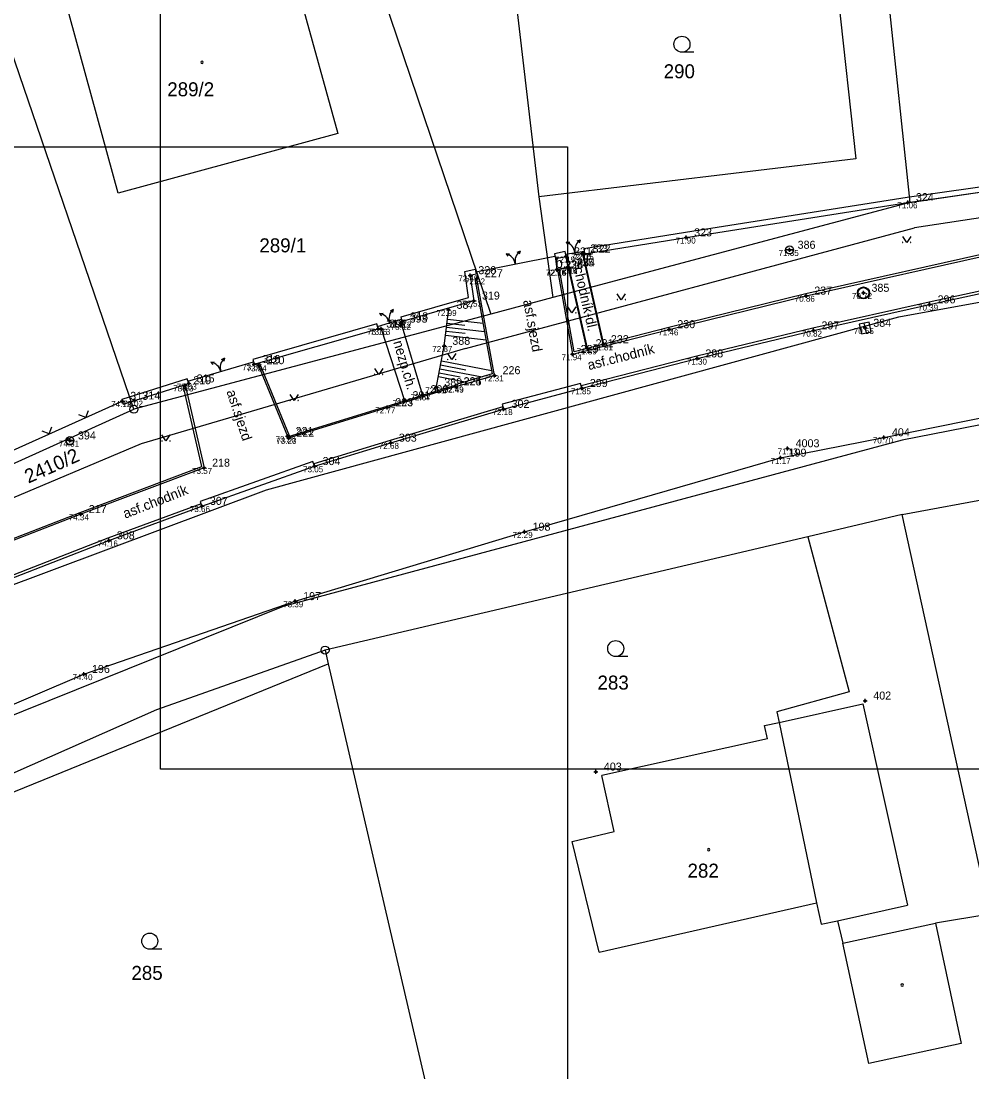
# Model space of a CAD drawing. Extents: x -454285 to -453563, y -1108687 to -1108249.
# Drawn here: x -453975.4 to -453927.9, y -1108516.1 to -1108463.6 of the extents above; entities that cross this region are included whole.
import ezdxf

# ---------------------------------------------------------------- set-up
doc = ezdxf.new("R2010")
doc.units = 0
for name, color, linetype in [('1', 7, 'Continuous'), ('14', 7, 'Continuous'), ('15', 7, 'Continuous'), ('2', 7, 'Continuous'), ('23', 7, 'Continuous'), ('25', 7, 'Continuous'), ('28', 7, 'Continuous'), ('beton', 7, 'Continuous'), ('BODY_T1_2018', 7, 'Continuous'), ('CISLA_T1_2018', 7, 'Continuous'), ('nezp.chodník', 7, 'Continuous'), ('obrubník', 7, 'Continuous'), ('okraj asf.komunikace', 7, 'Continuous'), ('oplocení', 7, 'Continuous'), ('rámy', 7, 'Continuous'), ('sloup', 7, 'Continuous'), ('svahy', 7, 'Continuous'), ('svahy-hrana', 7, 'Continuous'), ('T', 7, 'Continuous'), ('uliční vpusť', 7, 'Continuous'), ('VYSKY_T1_2018', 7, 'Continuous'), ('zeleň', 7, 'Continuous'), ('šachtice', 7, 'Continuous')]:
    doc.layers.add(name, color=color, linetype=linetype)

# ---------------------------------------------------------------- blocks, each defined once
blk = doc.blocks.new('Z402')
for start, end in [(0, 180), (180, 0)]:
    blk.add_arc((0, 0), 0.15, start, end)
blk = doc.blocks.new('Z105')
for radius in [0.5, 0.01]:
    blk.add_circle((0, 0), radius)
blk = doc.blocks.new('Z3040')
blk.add_line((1.5, 0), (0, 0))
blk.add_circle((0, 1), 1)
blk = doc.blocks.new('EL.SLOUP')
blk.add_line((0.4, 0), (-0.4, 0))
blk.add_line((0.4, 0), (-0.4, 0))
blk.add_lwpolyline([(0.4, 0), (-0.4, 0)])
blk.add_lwpolyline([(0.4, 0), (-0.4, 0)])
blk.add_circle((0, 0), 0.4)
blk.add_circle((0, 0), 0.4)
for start, end in [(270, 0), (270, 0), (180, 270), (180, 270)]:
    blk.add_arc((0, 0), 0.4, start, end)
blk = doc.blocks.new('šachtice_kruh_velká')
for radius in [0.5, 0.495, 0.495, 0.455, 0.455, 0.45]:
    blk.add_circle((0, 0), radius)
blk = doc.blocks.new('vpusť')
for p, q in [((0.25, 0.25), (-0.25, 0.25)), ((-0.25, 0.25), (-0.25, -0.25)), ((-0.25, 0), (0.25, 0)), ((0.25, -0.25), (0.25, 0.25)), ((-0.25, -0.25), (0.25, -0.25))]:
    blk.add_line(p, q)
blk = doc.blocks.new('PARK')
for p, q in [((0, 0), (-1, 1.5)), ((1, 1.5), (0, 0))]:
    blk.add_line(p, q)
for centre, start, end in [((-1, 0), 0, 180), ((1, 0), 0, 180), ((1, 0), 180, 0), ((-1, 0), 180, 0)]:
    blk.add_arc(centre, 0.05, start, end)
blk = doc.blocks.new('BRANKA')
for p, q in [((-0.351, 0.589), (-0.179, 0.552)), ((-0.351, 0.589), (-0.284, 0.449)), ((0.361, 0.583), (0.188, 0.549)), ((0.361, 0.583), (0.291, 0.445))]:
    blk.add_line(p, q)
for centre, start, end in [((-0.618, 0.03), 357.1751, 64.4688), ((0.619, 0.02), 114.5895, 181.8832)]:
    blk.add_arc(centre, 0.619, start, end)
blk = doc.blocks.new('PLOT05')
for q in [(-0.265, 0.265), (0.265, 0.265)]:
    blk.add_line((0, 0), q)
blk = doc.blocks.new('POINT_DISPLAY')
for p, q in [((-0.1, 0), (0.1, 0)), ((0, -0.1), (0, 0.1))]:
    blk.add_line(p, q)
blk.add_circle((0, 0), 0.05)
blk = doc.blocks.new('t1_2018')
at = {"layer": 'BODY_T1_2018'}
for p in [(-453931.05, -1108472.62), (-453942.13, -1108474.38), (-453947.32, -1108475.18), (-453947.2, -1108475.19), (-453936.96, -1108475), (-453948.13, -1108475.33), (-453952.91, -1108476.27), (-453948.59, -1108475.98), (-453948.56, -1108475.99), (-453948.02, -1108475.88), (-453947.97, -1108475.88), (-453952.58, -1108476.42), (-453936.13, -1108477.29), (-453933.27, -1108477.15), (-453952.73, -1108477.54), (-453929.97, -1108477.73), (-453954, -1108478), (-453957.51, -1108478.94), (-453957.36, -1108478.94), (-453956.34, -1108478.69), (-453956.31, -1108478.58), (-453942.97, -1108478.97), (-453933.18, -1108478.9), (-453935.77, -1108479.03), (-453954.21, -1108479.8), (-453947.05, -1108479.92), (-453946.29, -1108479.72), (-453947.8, -1108480.21), (-453941.57, -1108480.43), (-453963.7, -1108480.71), (-453963.49, -1108480.77), (-453951.7, -1108481.27), (-453967.15, -1108481.77), (-453966.98, -1108481.68), (-453954.61, -1108481.87), (-453953.65, -1108481.82), (-453953.64, -1108481.83), (-453947.34, -1108481.91), (-453970.3, -1108482.55), (-453969.69, -1108482.53), (-453956.2, -1108482.52), (-453955.3, -1108482.22), (-453957.06, -1108482.87), (-453951.25, -1108482.95), (-453972.91, -1108484.53), (-453962.04, -1108484.31), (-453962, -1108484.39), (-453956.88, -1108484.64), (-453932.25, -1108484.37), (-453937.06, -1108484.92), (-453937.41, -1108485.39), (-453966.21, -1108485.89), (-453960.69, -1108485.81), (-453966.32, -1108487.8), (-453972.37, -1108488.21), (-453950.2, -1108489.09), (-453970.97, -1108489.52), (-453961.66, -1108492.56), (-453972.21, -1108496.2), (-453933.18, -1108497.53), (-453946.64, -1108501.08)]:
    blk.add_blockref('POINT_DISPLAY', p, dxfattribs=at)
at = {"layer": 'CISLA_T1_2018'}
for s, p in [('324', (-453930.65, -1108472.56)), ('323', (-453941.73, -1108474.32)), ('386', (-453936.56, -1108474.94)), ('321', (-453947.73, -1108475.27)), ('233', (-453946.92, -1108475.12)), ('322', (-453946.8, -1108475.13)), ('236', (-453948.19, -1108475.92)), ('228', (-453948.16, -1108475.93)), ('235', (-453947.62, -1108475.82)), ('234', (-453947.57, -1108475.82)), ('320', (-453952.51, -1108476.21)), ('227', (-453952.18, -1108476.36)), ('385', (-453932.87, -1108477.09)), ('319', (-453952.33, -1108477.48)), ('237', (-453935.73, -1108477.23)), ('296', (-453929.57, -1108477.67)), ('387', (-453953.6, -1108477.94)), ('393', (-453955.94, -1108478.63)), ('318', (-453955.91, -1108478.52)), ('317', (-453957.11, -1108478.88)), ('392', (-453956.96, -1108478.88)), ('230', (-453942.57, -1108478.91)), ('297', (-453935.37, -1108478.97)), ('384', (-453932.78, -1108478.84)), ('388', (-453953.81, -1108479.74)), ('232', (-453945.89, -1108479.66)), ('229', (-453947.4, -1108480.15)), ('231', (-453946.65, -1108479.86)), ('316', (-453963.3, -1108480.65)), ('220', (-453963.09, -1108480.71)), ('298', (-453941.17, -1108480.37)), ('226', (-453951.3, -1108481.21)), ('219', (-453966.75, -1108481.71)), ('315', (-453966.58, -1108481.62)), ('389', (-453954.21, -1108481.81)), ('224', (-453953.25, -1108481.76)), ('225', (-453953.24, -1108481.77)), ('299', (-453946.94, -1108481.85)), ('390', (-453954.9, -1108482.16)), ('313', (-453969.9, -1108482.49)), ('314', (-453969.29, -1108482.47)), ('223', (-453956.66, -1108482.81)), ('391', (-453955.8, -1108482.46)), ('302', (-453950.85, -1108482.89)), ('394', (-453972.51, -1108484.47)), ('221', (-453961.64, -1108484.25)), ('222', (-453961.6, -1108484.33)), ('404', (-453931.85, -1108484.31)), ('303', (-453956.48, -1108484.58)), ('4003', (-453936.66, -1108484.86)), ('199', (-453937.01, -1108485.33)), ('218', (-453965.81, -1108485.83)), ('304', (-453960.29, -1108485.75)), ('217', (-453971.97, -1108488.15)), ('307', (-453965.92, -1108487.74)), ('198', (-453949.8, -1108489.03)), ('308', (-453970.57, -1108489.46)), ('197', (-453961.26, -1108492.5)), ('196', (-453971.81, -1108496.14)), ('402', (-453932.78, -1108497.47)), ('403', (-453946.24, -1108501.02))]:
    blk.add_text(s, height=0.4, dxfattribs=at).set_placement(p)
at = {"layer": 'VYSKY_T1_2018'}
for s, p in [('71.06', (-453931.575, -1108472.92)), ('71.90', (-453942.655, -1108474.68)), ('72.16', (-453947.87, -1108475.48)), ('72.15', (-453947.75, -1108475.49)), ('71.35', (-453937.51, -1108475.3)), ('72.19', (-453948.68, -1108475.63)), ('72.16', (-453949.14, -1108476.28)), ('72.16', (-453949.11, -1108476.29)), ('72.16', (-453948.57, -1108476.18)), ('72.17', (-453948.52, -1108476.18)), ('72.49', (-453953.51, -1108476.57)), ('72.32', (-453953.18, -1108476.72)), ('70.86', (-453936.705, -1108477.59)), ('70.72', (-453933.845, -1108477.45)), ('72.53', (-453953.33, -1108477.84)), ('70.39', (-453930.545, -1108478.03)), ('72.99', (-453954.6, -1108478.3)), ('73.12', (-453956.89, -1108478.99)), ('73.12', (-453956.86, -1108478.88)), ('73.16', (-453958.06, -1108479.24)), ('73.13', (-453957.91, -1108479.24)), ('71.46', (-453943.52, -1108479.27)), ('70.82', (-453936.345, -1108479.33)), ('70.55', (-453933.755, -1108479.2)), ('72.87', (-453954.81, -1108480.1)), ('71.89', (-453947.6, -1108480.22)), ('71.81', (-453946.79, -1108480.02)), ('71.94', (-453948.35, -1108480.51)), ('71.30', (-453942.095, -1108480.73)), ('73.55', (-453964.3, -1108481.01)), ('73.54', (-453964.09, -1108481.07)), ('72.31', (-453952.25, -1108481.57)), ('73.63', (-453967.75, -1108482.07)), ('73.63', (-453967.58, -1108481.98)), ('72.61', (-453955.16, -1108482.17)), ('72.49', (-453954.25, -1108482.12)), ('72.49', (-453954.24, -1108482.13)), ('71.85', (-453947.89, -1108482.21)), ('74.12', (-453970.85, -1108482.85)), ('74.02', (-453970.265, -1108482.83)), ('72.73', (-453956.8, -1108482.82)), ('72.67', (-453955.9, -1108482.52)), ('72.77', (-453957.66, -1108483.17)), ('72.18', (-453951.8, -1108483.25)), ('74.31', (-453973.46, -1108484.83)), ('73.26', (-453962.64, -1108484.61)), ('73.23', (-453962.6, -1108484.69)), ('72.68', (-453957.48, -1108484.94)), ('70.70', (-453932.8, -1108484.67)), ('71.13', (-453937.56, -1108485.22)), ('71.17', (-453937.91, -1108485.69)), ('73.57', (-453966.81, -1108486.19)), ('73.05', (-453961.265, -1108486.11)), ('73.66', (-453966.92, -1108488.1)), ('74.34', (-453972.97, -1108488.51)), ('72.29', (-453950.8, -1108489.39)), ('74.16', (-453971.52, -1108489.82)), ('73.39', (-453962.26, -1108492.86)), ('74.40', (-453972.785, -1108496.5))]:
    blk.add_text(s, height=0.3, dxfattribs=at).set_placement(p)

msp = doc.modelspace()

# ---------------------------------------------------------------- linework, layer by layer
at = {"layer": '1'}
for p, q in [((-453933.537, -1108448.061), (-453930.957, -1108472.621)), ((-453969.717, -1108482.961), (-453980.277, -1108452.101)), ((-453959.327, -1108456.231), (-453951.887, -1108478.201)), ((-453951.237, -1108457.361), (-453949.487, -1108472.341)), ((-453962.557, -1108458.211), (-453959.527, -1108469.181)), ((-453970.507, -1108472.161), (-453973.507, -1108461.221)), ((-453897.257, -1108468.871), (-453930.727, -1108473.891)), ((-453959.527, -1108469.181), (-453970.507, -1108472.161)), ((-453930.957, -1108472.621), (-453909.307, -1108469.461)), ((-453949.487, -1108472.341), (-453948.787, -1108477.381)), ((-453930.957, -1108472.621), (-453948.787, -1108477.381)), ((-453953.147, -1108479.931), (-453930.727, -1108473.891)), ((-453948.787, -1108477.381), (-453951.887, -1108478.201)), ((-453951.887, -1108478.201), (-453969.717, -1108482.961)), ((-453953.147, -1108479.931), (-453969.347, -1108484.681)), ((-453987.677, -1108491.051), (-453969.717, -1108482.961)), ((-453969.347, -1108484.681), (-454124.757, -1108550.421)), ((-453931.337, -1108488.221), (-453925.217, -1108487.081)), ((-453931.337, -1108488.221), (-453936.047, -1108489.331)), ((-453926.957, -1108508.191), (-453931.337, -1108488.221)), ((-453936.047, -1108489.331), (-453960.167, -1108495.001)), ((-453936.047, -1108489.331), (-453933.977, -1108497.081)), ((-453960.167, -1108495.001), (-453968.587, -1108497.991)), ((-453960.167, -1108495.001), (-453960.007, -1108495.681)), ((-453960.007, -1108495.681), (-453948.847, -1108543.851)), ((-453933.977, -1108497.081), (-453937.597, -1108498.091)), ((-453968.587, -1108497.991), (-453982.407, -1108504.081)), ((-453937.597, -1108498.091), (-453937.487, -1108498.611)), ((-453938.207, -1108498.771), (-453937.487, -1108498.611)), ((-453938.057, -1108499.431), (-453938.207, -1108498.771)), ((-453938.057, -1108499.431), (-453946.347, -1108501.261)), ((-453945.727, -1108504.061), (-453946.347, -1108501.261)), ((-453947.827, -1108504.561), (-453945.727, -1108504.061)), ((-453946.477, -1108510.101), (-453947.827, -1108504.561)), ((-453946.477, -1108510.101), (-453935.617, -1108507.621)), ((-453935.617, -1108507.621), (-453935.377, -1108508.691)), ((-453926.957, -1108508.191), (-453929.677, -1108508.651)), ((-453935.377, -1108508.691), (-453934.567, -1108508.521)), ((-453934.567, -1108508.521), (-453934.297, -1108509.641)), ((-453929.677, -1108508.651), (-453928.397, -1108514.661)), ((-453933.007, -1108515.651), (-453934.297, -1108509.641)), ((-453928.397, -1108514.661), (-453933.007, -1108515.651))]:
    msp.add_line(p, q, dxfattribs=at)
at = {"layer": '2'}
for p, q in [((-453936.057, -1108448.321), (-453933.657, -1108470.441)), ((-453933.657, -1108470.441), (-453949.487, -1108472.341)), ((-453931.507, -1108478.341), (-453899.627, -1108472.581)), ((-453963.087, -1108486.981), (-453931.507, -1108478.341)), ((-453898.937, -1108478.211), (-453931.337, -1108484.501)), ((-453931.337, -1108484.501), (-453962.267, -1108492.821)), ((-453990.237, -1108497.151), (-453963.087, -1108486.981)), ((-453962.267, -1108492.821), (-453988.537, -1108503.411)), ((-453982.257, -1108504.751), (-453960.007, -1108495.681)), ((-453937.487, -1108498.611), (-453933.297, -1108497.691)), ((-453933.297, -1108497.691), (-453931.077, -1108507.751)), ((-453937.487, -1108498.611), (-453935.617, -1108507.621)), ((-453934.567, -1108508.521), (-453931.077, -1108507.751)), ((-453934.297, -1108509.641), (-453929.677, -1108508.651))]:
    msp.add_line(p, q, dxfattribs=at)
at = {"layer": 'beton'}
msp.add_lwpolyline([(-453948.66, -1108475.434), (-453948.59, -1108475.98), (-453948.02, -1108475.88), (-453948.13, -1108475.33)], dxfattribs=at)
at = {"layer": 'nezp.chodník'}
for points in [[(-453955.3, -1108482.22), (-453956.34, -1108478.69)], [(-453957.36, -1108478.94), (-453956.2, -1108482.52)]]:
    msp.add_lwpolyline(points, dxfattribs=at)
at = {"layer": 'obrubník'}
for points in [[(-453915.478, -1108472.822), (-453916.439, -1108473.002), (-453926.341, -1108474.992), (-453936.153, -1108477.193), (-453942.994, -1108478.873), (-453947.721, -1108480.086), (-453948.462, -1108475.972), (-453948.56, -1108475.99), (-453947.8, -1108480.21), (-453942.97, -1108478.97), (-453936.13, -1108477.29), (-453926.32, -1108475.09), (-453916.42, -1108473.1), (-453915.46, -1108472.92)], [(-453947.34, -1108481.91), (-453941.57, -1108480.43), (-453935.77, -1108479.03), (-453929.97, -1108477.73), (-453922.14, -1108476.03), (-453915.3, -1108474.61), (-453915.324, -1108474.493), (-453922.165, -1108475.913), (-453929.996, -1108477.613), (-453935.797, -1108478.913), (-453941.599, -1108480.314), (-453947.37, -1108481.794)], [(-453948.019, -1108475.891), (-453947.102, -1108479.928), (-453947.053, -1108479.915), (-453947.97, -1108475.88)], [(-453951.25, -1108482.95), (-453947.34, -1108481.91), (-453947.404, -1108481.668), (-453951.314, -1108482.708)], [(-453951.283, -1108482.835), (-453956.915, -1108484.525), (-453960.728, -1108485.696), (-453960.69, -1108485.81), (-453956.88, -1108484.64), (-453951.25, -1108482.95)], [(-453966.32, -1108487.8), (-453960.69, -1108485.81), (-453960.774, -1108485.575), (-453966.403, -1108487.564)], [(-453966.361, -1108487.687), (-453971.013, -1108489.408), (-453978.464, -1108492.308), (-453986.834, -1108495.588), (-453986.79, -1108495.7), (-453978.42, -1108492.42), (-453970.97, -1108489.52), (-453966.32, -1108487.8)]]:
    msp.add_lwpolyline(points, close=True, dxfattribs=at)
for points in [[(-453947.342, -1108475.085), (-453946.285, -1108479.718), (-453946.237, -1108479.705), (-453947.292, -1108475.077)], [(-453952.678, -1108476.438), (-453951.815, -1108481.199), (-453953.668, -1108481.734), (-453953.64, -1108481.83), (-453951.7, -1108481.27), (-453952.58, -1108476.42)], [(-453963.534, -1108480.663), (-453962.04, -1108484.31), (-453961.944, -1108484.282), (-453963.437, -1108480.635)], [(-453967.158, -1108481.736), (-453966.21, -1108485.89), (-453972.37, -1108488.21), (-453977.99, -1108490.39), (-453984.54, -1108492.92), (-453984.577, -1108492.827), (-453978.026, -1108490.297), (-453972.406, -1108488.117), (-453966.327, -1108485.827), (-453967.254, -1108481.766)], [(-453962, -1108484.39), (-453957.06, -1108482.87), (-453953.65, -1108481.82), (-453953.665, -1108481.772), (-453957.075, -1108482.822), (-453962.015, -1108484.342)]]:
    msp.add_lwpolyline(points, dxfattribs=at)
at = {"layer": 'okraj asf.komunikace'}
msp.add_lwpolyline([(-453982.81, -1108509.99), (-453983.85, -1108505.12), (-453983.55, -1108502.51), (-453982.48, -1108500.59), (-453972.21, -1108496.2), (-453961.66, -1108492.56), (-453950.2, -1108489.09), (-453937.41, -1108485.39), (-453932.25, -1108484.37), (-453926.75, -1108483.25), (-453917, -1108481.33), (-453912.35, -1108480.49), (-453907.08, -1108479.77), (-453900.36, -1108478.91), (-453893.38, -1108478.37), (-453887.02, -1108478.23), (-453881.35, -1108478.03), (-453874.87, -1108478.15), (-453872.62, -1108479.21), (-453871.56, -1108480.92), (-453871.45, -1108482.5)], dxfattribs=at)
at = {"layer": 'oplocení'}
for p, q in [((-453948.154, -1108475.207), (-453947.22, -1108475.067)), ((-453952.642, -1108476.09), (-453948.684, -1108475.312)), ((-453957.544, -1108478.82), (-453956.34, -1108478.459)), ((-453967.017, -1108481.561), (-453963.734, -1108480.59))]:
    msp.add_line(p, q, dxfattribs=at)
for points in [[(-453916.04, -1108468.251), (-453915.879, -1108470.206), (-453931.087, -1108472.373), (-453942.169, -1108474.133), (-453947.239, -1108474.943), (-453947.2, -1108475.19), (-453942.13, -1108474.38), (-453931.05, -1108472.62), (-453915.61, -1108470.42), (-453915.77, -1108468.48), (-453915.791, -1108468.231)], [(-453948.178, -1108475.085), (-453948.708, -1108475.189), (-453948.66, -1108475.434), (-453948.13, -1108475.33)], [(-453956.371, -1108478.338), (-453953.006, -1108477.374), (-453953.191, -1108476.07), (-453952.666, -1108475.967), (-453952.618, -1108476.213), (-453952.91, -1108476.27), (-453952.73, -1108477.54), (-453956.31, -1108478.58)], [(-453963.7, -1108480.71), (-453957.51, -1108478.94), (-453957.579, -1108478.7), (-453963.769, -1108480.47)], [(-453970.251, -1108482.706), (-453966.98, -1108481.68), (-453967.055, -1108481.441), (-453970.326, -1108482.467)]]:
    msp.add_lwpolyline(points, close=True, dxfattribs=at)
msp.add_lwpolyline([(-453992.51, -1108492.57), (-453989.05, -1108490.98), (-453987.18, -1108490.14), (-453985.94, -1108489.59), (-453970.3, -1108482.55)], dxfattribs=at)
at = {"layer": 'rámy'}
for points in [[(-453968.38, -1108440.904), (-453869.211, -1108440.904), (-453869.211, -1108500.955), (-453968.38, -1108500.955)], [(-454047.225, -1108469.854), (-453948.057, -1108469.854), (-453948.057, -1108529.906), (-454047.225, -1108529.906)]]:
    msp.add_lwpolyline(points, close=True, dxfattribs=at)
at = {"layer": 'svahy'}
for p, q in [((-453954.1, -1108478.853), (-453952.2, -1108479.074)), ((-453954.076, -1108478.654), (-453953.187, -1108478.758)), ((-453954.053, -1108478.456), (-453952.275, -1108478.663)), ((-453954.146, -1108479.25), (-453952.125, -1108479.486)), ((-453954.123, -1108479.052), (-453953.173, -1108479.162)), ((-453954.43, -1108480.938), (-453952.321, -1108481.345)), ((-453954.392, -1108480.741), (-453953.138, -1108480.984)), ((-453954.354, -1108480.545), (-453951.845, -1108481.03)), ((-453954.506, -1108481.33), (-453953.167, -1108481.589)), ((-453954.468, -1108481.134), (-453953.413, -1108481.338))]:
    msp.add_line(p, q, dxfattribs=at)
at = {"layer": 'svahy-hrana'}
msp.add_lwpolyline([(-453954.65, -1108482.076), (-453954.21, -1108479.8), (-453953.989, -1108477.906)], dxfattribs=at)

# ---------------------------------------------------------------- block references
msp.add_blockref('t1_2018', (0, 0))
at = {"layer": '23', "xscale": 0.4, "yscale": 0.4000000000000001}
for p in [(-453942.338, -1108465.119), (-453945.649, -1108495.32), (-453968.924, -1108509.945)]:
    msp.add_blockref('Z3040', p, dxfattribs=at)
at = {"layer": '25', "xscale": 0.4, "yscale": 0.4000000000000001}
for p in [(-453966.308, -1108465.62), (-453940.999, -1108504.978), (-453931.337, -1108511.741)]:
    msp.add_blockref('Z402', p, dxfattribs=at)
at = {"layer": '28', "xscale": 0.4, "yscale": 0.4000000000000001}
for p in [(-453969.717, -1108482.961), (-453960.167, -1108495.001)]:
    msp.add_blockref('Z105', p, dxfattribs=at)
at = {"layer": 'oplocení'}
for name, p, rotation in [('BRANKA', (-453947.687, -1108475.137), 8.568172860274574), ('BRANKA', (-453950.663, -1108475.701), 11.12540564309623), ('BRANKA', (-453956.942, -1108478.639), 16.693834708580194), ('BRANKA', (-453965.376, -1108481.075), 16.474815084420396), ('PLOT05', (-453972.124, -1108483.371), 24.233838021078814), ('PLOT05', (-453973.948, -1108484.192), 24.233838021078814)]:
    msp.add_blockref(name, p, dxfattribs=dict(at, rotation=rotation))
at = {"layer": 'sloup', "xscale": 0.5, "yscale": 0.5}
for p in [(-453936.96, -1108475), (-453972.91, -1108484.53)]:
    msp.add_blockref('EL.SLOUP', p, dxfattribs=at)
at = {"layer": 'uliční vpusť', "rotation": 102.6333619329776}
msp.add_blockref('vpusť', (-453933.18, -1108478.9), dxfattribs=at)
at = {"layer": 'zeleň', "xscale": 0.2, "yscale": 0.20000000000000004}
for p in [(-453931.112, -1108474.625), (-453945.372, -1108477.487), (-453947.839, -1108478.136), (-453953.837, -1108480.474), (-453957.483, -1108481.217), (-453961.711, -1108482.528), (-453968.119, -1108484.541)]:
    msp.add_blockref('PARK', p, dxfattribs=at)
at = {"layer": 'šachtice', "xscale": 0.6, "yscale": 0.6}
msp.add_blockref('šachtice_kruh_velká', (-453933.27, -1108477.15), dxfattribs=at)

# ---------------------------------------------------------------- texts
at = {"layer": '14'}
for s, p in [('290', (-453943.252, -1108466.421)), ('289/1', (-453963.449, -1108475.12)), ('283', (-453946.557, -1108496.971)), ('285', (-453969.84, -1108511.481))]:
    msp.add_text(s, height=0.7, dxfattribs=at).set_placement(p)
msp.add_text('2410/2', height=0.7, rotation=23.949, dxfattribs=at).set_placement((-453974.987, -1108486.681))
at = {"layer": '15'}
for s, p in [('289/2', (-453968.05, -1108467.321)), ('282', (-453942.06, -1108506.371))]:
    msp.add_text(s, height=0.7, dxfattribs=at).set_placement(p)
at = {"layer": 'T'}
msp.add_text('b.', height=0.5, dxfattribs=at).set_placement((-453948.659, -1108475.894))
for s, rotation, p in [('chodník-dl.', 282.8477, (-453947.752, -1108475.914)), ('asf.sjezd', 280.2092, (-453950.275, -1108477.532)), ('nezp.ch.', 286.4159, (-453956.767, -1108479.605)), ('asf.chodník', 14.3862, (-453946.985, -1108481.006)), ('asf.sjezd', 288.1208, (-453965.099, -1108482.077)), ('asf.chodník', 21.4825, (-453970.148, -1108488.433))]:
    msp.add_text(s, height=0.5, rotation=rotation, dxfattribs=at).set_placement(p)

doc.saveas('drawing.dxf')
